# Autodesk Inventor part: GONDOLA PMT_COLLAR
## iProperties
Shininess: 64.0
Length Units: 11272
Angle Units: 11279
Time Units: 11290
Mass Units: 11286
Length Display Precision: 3
Angle Display Precision: 2
Compacted: True
Part Number: GONDOLA PMT_COLLAR
Document SubType Name: Modeling
Created: 2004-08
Designer: John Blackburn
Manufacturer: Standard
Standards Organization: Custom
Density: 0.0
Volumn: 0.0
Area: 0.0
PropertySet Name: Model Information
Control State: 0
Master: False
Checked Out: False
Author: John Blackburn
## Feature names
1. Base1
